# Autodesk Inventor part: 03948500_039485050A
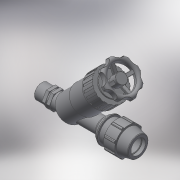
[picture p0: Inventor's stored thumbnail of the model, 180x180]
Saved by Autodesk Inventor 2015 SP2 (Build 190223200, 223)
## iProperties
Created: 2017-02
Part Number: 03948500_039485050A
Material: Generic
Description: PLASSON ANGLE SEAT VALVE 50-1.1/2"
Document SubType Name: Modeling
Designer: KIM
Mass: 1593.1 g
Surface Area: 1791.15 cm^2
Volume: 1593.1 cm^3
Density: 1 g/cm^3
Appearance: Default
Author: KIM
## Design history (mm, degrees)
derived "03048-03948.ipt"
feature "Solid1::03048-03948.ipt"
tag "TaggingFeature1"
body "Solid1"
other parameters: "d4" = 10.79167, "d5" = 25.9, "d7" = 96, "d11" = 3.7, "d13" = 120 deg, "d15" = 12 deg, "d16" = 83.52, "d18" = 2.5, "d19" = 35 deg, "d20" = 17.5 deg, "d21" = 89.28, "d23" = 0, "d25" = 360 deg, "d27" = 1.92, "d33" = 1, "d42" = 31.08, "d43" = 2.88, "d46" = 1.5, "d63" = 93, "d67" = 72, "d96" = 6.475, "d128" = 259, "d159" = 2, "d165" = 186.3, "d167" = 111.78, "d168" = 33.534, "d169" = 33.534, "d170" = 90 deg, "d171" = 70 deg, "d172" = 26.8272, "d173" = 78.246, "d174" = 78.246, "d175" = 100.602, "d176" = 135 deg, "d177" = 89.424, "d178" = 83.835, "d179" = 46.575, "d180" = 186.3, "d182" = 26.8272, "d183" = 73.7748, "d190" = 45 deg, "d191" = 51.8, "d192" = 4.14, "d193" = 4.52, "d194" = 2.26, "d195" = 97.58394, "d198" = 0, "d199" = 41.9175, "d200" = 113, "d204" = 360 deg, "d209" = 0, "d213" = 5.589, "d216" = 360 deg, "d220" = 95.013, "d221" = 3.39, "d222" = 3.39, "d223" = 6.78, "d227" = 3.39, "d229" = 0, "d230" = 1.035, "d232" = 360 deg, "d234" = 1.035, "d235" = 1.035, "d237" = 360 deg, "d239" = 1.656, "d241" = 1.035, "d249" = 47.803, "d250" = 45 deg, "d252" = 259, "d253" = 22, "d254" = 7.33333, "d255" = 3.66667, "d256" = 56, "d258" = 0, "d260" = 0, "d261" = 0.95606, "d265" = 0, "d266" = 207, "E_" = 96, "A_" = 207, "l_" = 93, "H_" = 259, "d224" = 113, "G_" = 47.803, "l_2" = 22, "d202" = 100.602, "d214" = 111.78, "d218" = 111.78, "d225" = 111.78, "d226" = 78.246
